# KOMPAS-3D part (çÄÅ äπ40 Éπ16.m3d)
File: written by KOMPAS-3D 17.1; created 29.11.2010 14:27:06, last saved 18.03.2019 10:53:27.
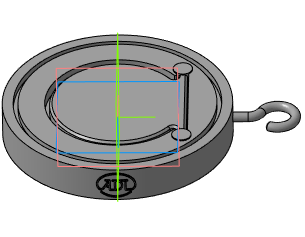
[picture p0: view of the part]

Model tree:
1. Плоскость XY
2. Плоскость ZX
3. Плоскость ZY
4. Ось X
5. Ось Y
6. Ось Z
7. Начало координат
8. Операция без истории:2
